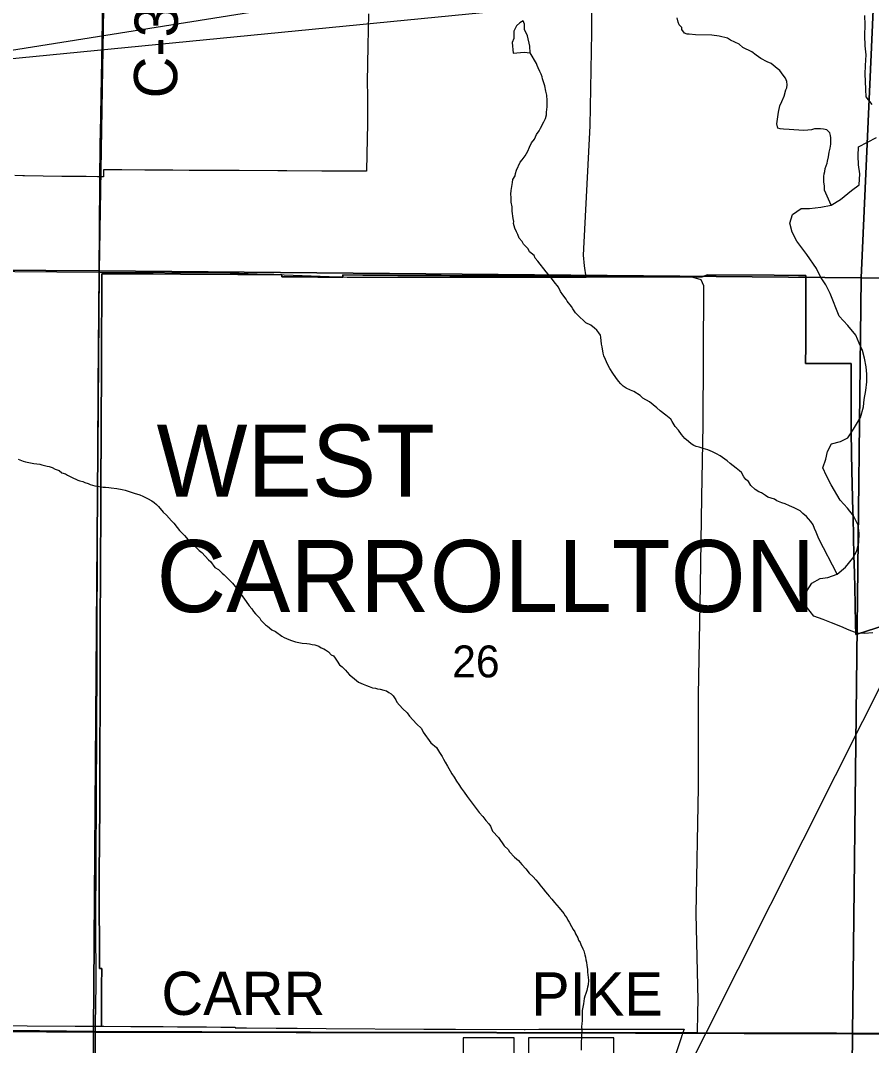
# Model space of a CAD drawing. Extents: x 0 to 34, y 0 to 22.
# Drawn here: x 3.924 to 5.042, y 14.765 to 16.112 of the extents above; entities that cross this region are included whole.
import ezdxf

# ---------------------------------------------------------------- set-up
doc = ezdxf.new("R2010")
doc.units = 0
for name, color, linetype in [('GM_X_Corporation_Text', 7, 'Continuous'), ('GM_X_County_Road', 7, 'Continuous'), ('GM_X_County_Road_Text', 7, 'Continuous'), ('GM_X_Interchange_Ramps', 7, 'Continuous'), ('GM_X_Interstate_Route', 7, 'Continuous'), ('GM_X_Minor_River', 7, 'Continuous'), ('GM_X_Rail_Line', 7, 'Continuous'), ('GM_X_Section', 7, 'Continuous'), ('GM_X_Section_Text', 7, 'Continuous'), ('GM_X_Township_Road', 7, 'Continuous'), ('SH_Text', 7, 'Continuous')]:
    doc.layers.add(name, color=color, linetype=linetype)

msp = doc.modelspace()

# ---------------------------------------------------------------- linework, layer by layer
at = {"layer": 'GM_X_County_Road'}
for p, q in [((3.042, 14.7898), (4.0225, 14.783)), ((4.0225, 14.783), (4.0227, 14.793)), ((4.0225, 14.783), (4.8137, 14.7815)), ((4.8137, 14.7815), (5.1801, 14.7808))]:
    msp.add_line(p, q, dxfattribs=at)
for points in [[(4.0289, 15.9515), (4.0291, 15.9644), (4.0311, 16.0847), (4.0341, 16.2506), (4.035, 16.2928), (4.0387, 16.4512)], [(4.0272, 15.7814), (4.0281, 15.8988), (4.0289, 15.9515)], [(4.0227, 14.793), (4.0235, 14.8451), (4.0229, 14.9278), (4.0237, 15.0898), (4.0246, 15.2692), (4.0252, 15.4538), (4.026, 15.6304), (4.0272, 15.7814)], [(4.0179, 13.9751), (4.0177, 14.0006), (4.0192, 14.1613), (4.0205, 14.2715), (4.0208, 14.4334), (4.0216, 14.5324), (4.0225, 14.6549), (4.0225, 14.783)]]:
    msp.add_lwpolyline(points, dxfattribs=at)
at = {"layer": 'GM_X_Interchange_Ramps'}
for points in [[(4.3812, 16.1209), (4.3805, 16.0788), (4.3797, 16.0313), (4.3798, 16.0136), (4.3798, 16.0023), (4.3799, 15.9845), (4.3798, 15.9765), (4.3792, 15.9365), (4.3789, 15.9141), (4.3329, 15.9143), (4.3202, 15.9144), (4.2738, 15.9147), (4.262, 15.9147), (4.2115, 15.915), (4.2038, 15.9151), (4.158, 15.9153), (4.1455, 15.9154), (4.124, 15.9155), (4.0947, 15.9157), (4.0872, 15.9157), (4.057, 15.9159), (4.033, 15.916), (4.0329, 15.9067), (4.0253, 15.9068), (4.0102, 15.9071), (3.9781, 15.9075), (3.9294, 15.9082), (3.9272, 15.9082), (3.9166, 15.9084)], [(3.8063, 14.7923), (3.9957, 14.791), (4.0303, 14.7908), (4.0303, 14.7938), (4.0303, 14.7939), (4.0303, 14.794), (4.0303, 14.7941), (4.0303, 14.7945), (4.0305, 14.8212), (4.0306, 14.844), (4.0308, 14.8667), (4.0279, 14.8667), (4.0279, 14.8765), (4.0277, 14.9008), (4.0276, 14.9109), (4.0275, 14.935), (4.0275, 14.9407), (4.0272, 14.9897), (4.0272, 14.9907), (4.0282, 15.079), (4.0282, 15.0822), (4.0283, 15.126), (4.0286, 15.241), (4.0287, 15.27), (4.0287, 15.2827), (4.0287, 15.2909), (4.0289, 15.3364), (4.0289, 15.347), (4.029, 15.3595), (4.029, 15.3667), (4.0291, 15.3873), (4.0292, 15.4131), (4.0294, 15.4525), (4.0296, 15.4906), (4.0296, 15.5103), (4.0297, 15.5125), (4.0297, 15.5285), (4.0298, 15.5447), (4.0299, 15.578), (4.0303, 15.6573), (4.0304, 15.6876), (4.0307, 15.7568), (4.0308, 15.7795), (4.057, 15.7794), (4.0985, 15.7792), (4.1344, 15.779), (4.2095, 15.7786), (4.2243, 15.7785), (4.2568, 15.7784), (4.2676, 15.7783), (4.2676, 15.7755), (4.2811, 15.7754), (4.296, 15.7753), (4.2965, 15.7753), (4.3148, 15.7752), (4.3168, 15.7752), (4.3477, 15.775), (4.3477, 15.7779), (4.3738, 15.7777), (4.3927, 15.7776), (4.397, 15.7775), (4.4084, 15.7775), (4.4198, 15.7774), (4.4311, 15.7773), (4.4425, 15.7772), (4.4434, 15.7772), (4.4539, 15.7772), (4.4652, 15.7771), (4.4766, 15.777), (4.488, 15.7769), (4.4993, 15.7769), (4.5107, 15.7768), (4.5354, 15.7768), (4.5385, 15.7768), (4.5441, 15.7768), (4.5764, 15.7768), (4.6037, 15.7767), (4.6335, 15.7765), (4.642, 15.7765), (4.6695, 15.7763), (4.686, 15.7762), (4.728, 15.776), (4.8118, 15.7755), (4.8161, 15.7755), (4.8199, 15.7755), (4.8231, 15.7767), (4.8256, 15.7776), (4.8273, 15.7783), (4.9143, 15.7776), (4.9462, 15.7774), (4.9542, 15.7773), (4.9562, 15.7773), (4.956, 15.7046), (4.9559, 15.685), (4.9558, 15.6617), (4.9749, 15.6616), (5.0157, 15.6614), (5.0154, 15.5733), (5.0155, 15.568), (5.016, 15.548), (5.0161, 15.5433), (5.0166, 15.521), (5.0179, 15.4669), (5.0181, 15.4598), (5.0193, 15.409), (5.0198, 15.3865), (5.0203, 15.3662), (5.0208, 15.3454), (5.0214, 15.3183), (5.0217, 15.3066), (5.0217, 15.3055), (5.0316, 15.3087), (5.071, 15.3213)], [(5.071, 15.3213), (5.0316, 15.3087), (5.0217, 15.3055), (5.0217, 15.3066), (5.0214, 15.3183), (5.0208, 15.3454), (5.0203, 15.3662), (5.0198, 15.3865), (5.0193, 15.409), (5.0181, 15.4598), (5.0179, 15.4669), (5.0166, 15.521), (5.0161, 15.5433), (5.016, 15.5444), (5.016, 15.548), (5.0155, 15.568), (5.0154, 15.5733), (5.0157, 15.6614), (4.9749, 15.6616), (4.9558, 15.6617), (4.9559, 15.685), (4.956, 15.7046), (4.9562, 15.7773), (4.9542, 15.7773), (4.9462, 15.7774), (4.9143, 15.7776), (4.8273, 15.7783), (4.8256, 15.7776), (4.8231, 15.7767), (4.8199, 15.7755), (4.8161, 15.7755), (4.8118, 15.7755), (4.728, 15.776), (4.686, 15.7762), (4.6695, 15.7763), (4.642, 15.7765), (4.6335, 15.7765), (4.6037, 15.7767), (4.5764, 15.7768), (4.5441, 15.7768), (4.5385, 15.7768), (4.5354, 15.7768), (4.5107, 15.7768), (4.4993, 15.7769), (4.488, 15.7769), (4.4766, 15.777), (4.4652, 15.7771), (4.4539, 15.7772), (4.4425, 15.7772), (4.4311, 15.7773), (4.4198, 15.7774), (4.4084, 15.7775), (4.397, 15.7775), (4.3927, 15.7776), (4.3738, 15.7777), (4.3477, 15.7779), (4.3477, 15.775), (4.3168, 15.7752), (4.3148, 15.7752), (4.296, 15.7753), (4.2811, 15.7754), (4.2676, 15.7755), (4.2676, 15.7783), (4.2568, 15.7784), (4.2243, 15.7785), (4.2095, 15.7786), (4.1344, 15.779), (4.0985, 15.7792), (4.057, 15.7794), (4.0308, 15.7795), (4.0307, 15.7568), (4.0304, 15.6876), (4.0303, 15.6573), (4.0299, 15.578), (4.0298, 15.5447), (4.0298, 15.5436), (4.0297, 15.5285), (4.0297, 15.5125), (4.0296, 15.5103), (4.0296, 15.4906), (4.0296, 15.4884), (4.0294, 15.4525), (4.0292, 15.4131), (4.0291, 15.3873), (4.029, 15.3667), (4.029, 15.3595), (4.0289, 15.347), (4.0289, 15.3364), (4.0287, 15.2909), (4.0287, 15.2827), (4.0287, 15.27), (4.0286, 15.241), (4.0283, 15.1277), (4.0283, 15.126), (4.0282, 15.0822), (4.0282, 15.079), (4.0272, 14.9907), (4.0272, 14.9897), (4.0275, 14.9407), (4.0275, 14.935), (4.0276, 14.9109), (4.0277, 14.9008), (4.0279, 14.8765), (4.0279, 14.8667), (4.0308, 14.8667), (4.0306, 14.844), (4.0305, 14.8212), (4.0303, 14.7945), (4.0303, 14.7944), (4.0303, 14.7943), (4.0303, 14.7941), (4.0303, 14.794), (4.0303, 14.7908), (4.0337, 14.7908), (4.0689, 14.7905), (4.0926, 14.7903), (4.1115, 14.7902), (4.1305, 14.7901), (4.1494, 14.7899), (4.1683, 14.7898), (4.1873, 14.7897), (4.2062, 14.7896), (4.2062, 14.7886), (4.2209, 14.7885), (4.26, 14.7883), (4.265, 14.7882), (4.2874, 14.7881), (4.3256, 14.7878), (4.4539, 14.7871), (4.4747, 14.787), (4.4956, 14.7869), (4.5858, 14.7866), (4.5874, 14.7866), (4.6051, 14.7867), (4.6717, 14.7869), (4.6907, 14.7869), (4.7637, 14.7871), (4.7906, 14.787), (4.7961, 14.787), (4.7941, 14.7813), (4.7935, 14.7795), (4.7932, 14.7784), (4.7922, 14.7756), (4.7922, 14.7756), (4.7749, 14.7247)], [(4.5722, 14.7351), (4.5727, 14.7753), (4.567, 14.7753), (4.5055, 14.7755), (4.505, 14.6575)], [(4.7035, 14.7423), (4.7039, 14.7756), (4.6894, 14.7755), (4.6714, 14.7755), (4.601, 14.7753), (4.5916, 14.7753), (4.5912, 14.7349)]]:
    msp.add_lwpolyline(points, dxfattribs=at)
at = {"layer": 'GM_X_Interstate_Route'}
for points in [[(5.1798, 14.7813), (4.8134, 14.782), (4.0223, 14.7835), (3.0418, 14.7903)], [(3.0418, 14.7903), (4.0223, 14.7835), (4.8134, 14.782), (5.1798, 14.7813)]]:
    msp.add_lwpolyline(points, dxfattribs=at)
at = {"layer": 'GM_X_Minor_River'}
for points in [[(4.5859, 16.0708), (4.5939, 16.0699), (4.5933, 16.0787), (4.5902, 16.0921), (4.5865, 16.1005), (4.5863, 16.1073), (4.5845, 16.1119), (4.5803, 16.1094), (4.576, 16.1053), (4.5724, 16.0981)], [(4.9891, 15.8696), (4.9807, 15.8894), (4.9807, 15.8925), (4.9804, 15.8952), (4.9798, 15.8997), (4.9795, 15.9043), (4.9796, 15.9074), (4.9801, 15.9108), (4.9809, 15.9138), (4.9814, 15.9176), (4.9839, 15.9248), (4.9843, 15.9275), (4.986, 15.9331), (4.9869, 15.9392), (4.9878, 15.9445), (4.9887, 15.9499), (4.9889, 15.9582), (4.9886, 15.9613), (4.9876, 15.9647), (4.9835, 15.9687), (4.9793, 15.9695), (4.9751, 15.97), (4.9713, 15.9701), (4.9675, 15.9698), (4.9633, 15.9688), (4.9587, 15.9681), (4.9533, 15.9679), (4.9469, 15.968), (4.9404, 15.9686), (4.9343, 15.9691), (4.9267, 15.9693), (4.9221, 15.9701), (4.9191, 15.9706), (4.9181, 15.9767), (4.919, 15.9828), (4.92, 15.9919), (4.9218, 16.0003), (4.9246, 16.0059), (4.9274, 16.0127), (4.9299, 16.021), (4.9311, 16.0237), (4.9316, 16.0279), (4.931, 16.0321), (4.9292, 16.0363), (4.9262, 16.0406), (4.9218, 16.0464), (4.9185, 16.0491), (4.9103, 16.0558), (4.905, 16.0579), (4.8967, 16.0622), (4.8907, 16.0666), (4.8851, 16.0709), (4.8731, 16.0769), (4.8686, 16.0812), (4.8569, 16.0865), (4.8532, 16.0892), (4.8422, 16.0918), (4.8327, 16.0928), (4.811, 16.0933), (4.8026, 16.0942), (4.7999, 16.0943), (4.7965, 16.0955), (4.7932, 16.1006), (4.7929, 16.1032), (4.7896, 16.1068), (4.7881, 16.1102), (4.7871, 16.1156)], [(5.043, 16.0021), (5.0352, 16.0118), (5.0347, 16.0217), (5.0346, 16.0324), (5.0341, 16.0419), (5.0345, 16.0533), (5.0352, 16.0673), (5.034, 16.0792), (5.0336, 16.0925), (5.034, 16.1066), (5.0336, 16.1188)], [(4.5724, 16.0981), (4.5722, 16.0886), (4.5702, 16.0833), (4.5714, 16.0692), (4.5859, 16.0708)], [(4.572, 15.8456), (4.5721, 15.8482), (4.5714, 15.8521), (4.5701, 15.8616), (4.5702, 15.8643), (4.5699, 15.8674), (4.5689, 15.8735), (4.5687, 15.8796), (4.5684, 15.8842), (4.569, 15.8891), (4.5704, 15.8994), (4.5712, 15.9032), (4.574, 15.9081), (4.5745, 15.9111), (4.5757, 15.9156), (4.5806, 15.9262), (4.5833, 15.9292), (4.5873, 15.9344), (4.5909, 15.9408), (4.5929, 15.9457), (4.5953, 15.9514), (4.5993, 15.9562), (4.6021, 15.9623), (4.6057, 15.9671), (4.6073, 15.9709), (4.6117, 15.9792), (4.6141, 15.9837), (4.6154, 15.9882), (4.6154, 15.9917), (4.616, 15.9989), (4.6162, 16.0073), (4.6156, 16.0142), (4.6143, 16.0195), (4.6129, 16.0264), (4.6111, 16.0318), (4.6101, 16.0356), (4.6094, 16.0383), (4.6084, 16.0418), (4.6065, 16.0452), (4.6044, 16.0503), (4.6029, 16.0533), (4.6019, 16.056), (4.5939, 16.0699)], [(5.0442, 15.3078), (5.0331, 15.3066), (5.0236, 15.3073), (5.013, 15.311), (5.0018, 15.3162), (4.9897, 15.3208), (4.9788, 15.3253), (4.9667, 15.3298), (4.9568, 15.3419), (4.9529, 15.3515), (4.9578, 15.3631), (4.9637, 15.3729), (4.9749, 15.379), (4.9849, 15.3803), (4.9972, 15.3849), (5.0081, 15.3941), (5.0179, 15.4056), (5.0231, 15.4153), (5.0257, 15.4263), (5.026, 15.4385), (5.0248, 15.4492), (5.0187, 15.4615), (5.0109, 15.4713), (5.0013, 15.4822), (4.9893, 15.5023), (4.9832, 15.5139), (4.9785, 15.5243), (4.9823, 15.536), (4.9844, 15.5458), (4.9897, 15.556), (5.0015, 15.5591), (5.0112, 15.5641), (5.0187, 15.5753), (5.0279, 15.5907), (5.0317, 15.6046), (5.0327, 15.6141), (5.035, 15.6259), (5.0364, 15.6376), (5.0363, 15.6475), (5.0351, 15.6571), (5.0331, 15.6685), (5.0303, 15.6785), (5.026, 15.6882), (5.0217, 15.6989), (5.0114, 15.7114), (5, 15.7239), (4.9882, 15.7535), (4.9824, 15.7651), (4.9755, 15.7756), (4.9701, 15.7864), (4.9573, 15.805), (4.944, 15.8225), (4.9379, 15.8341), (4.9352, 15.846), (4.9385, 15.8573), (4.9498, 15.8654), (4.9608, 15.8654), (4.9757, 15.8669), (4.9891, 15.8696), (5.0015, 15.8772), (5.0159, 15.889), (5.026, 15.8963), (5.0271, 15.9108), (5.0252, 15.9226), (5.0247, 15.9344), (5.0251, 15.9462), (5.049, 15.9585)], [(4.9972, 15.3849), (4.973, 15.431), (4.9712, 15.4356), (4.9698, 15.4398), (4.9676, 15.4449), (4.9655, 15.4495), (4.9625, 15.4541), (4.9596, 15.4576), (4.957, 15.4604), (4.9521, 15.4643), (4.9484, 15.4682), (4.9409, 15.4718), (4.9345, 15.4746), (4.9288, 15.4771), (4.9247, 15.4787), (4.9179, 15.4811), (4.9149, 15.4835), (4.9062, 15.486), (4.9032, 15.488), (4.8976, 15.4915), (4.8942, 15.4931), (4.8893, 15.4959), (4.8837, 15.5014), (4.8808, 15.5064), (4.877, 15.5092), (4.8745, 15.5127), (4.8716, 15.5185), (4.8689, 15.5204), (4.8645, 15.524), (4.8607, 15.5271), (4.8566, 15.5303), (4.8525, 15.5338), (4.8435, 15.5401), (4.8387, 15.5429), (4.8334, 15.5457), (4.8274, 15.5481), (4.8213, 15.5498), (4.816, 15.5515), (4.8118, 15.5527), (4.8088, 15.5539), (4.8054, 15.5559), (4.8017, 15.5591), (4.7972, 15.563), (4.7928, 15.5684), (4.7888, 15.5739), (4.7843, 15.5789), (4.7803, 15.5855), (4.7785, 15.5886), (4.7721, 15.5937), (4.7646, 15.5996), (4.7602, 15.6035), (4.7505, 15.6114), (4.7418, 15.6162), (4.7381, 15.6197), (4.7298, 15.6248), (4.7257, 15.6265), (4.7197, 15.6293), (4.7159, 15.6317), (4.7129, 15.6348), (4.71, 15.6383), (4.7063, 15.643), (4.7026, 15.6488), (4.6986, 15.655), (4.6953, 15.6608), (4.6928, 15.6669), (4.6906, 15.6715), (4.6896, 15.675), (4.6883, 15.6834), (4.6876, 15.6869), (4.6867, 15.696), (4.686, 15.6987), (4.6842, 15.7018), (4.6812, 15.7053), (4.6782, 15.7081), (4.6734, 15.712), (4.667, 15.7152), (4.664, 15.7183), (4.6592, 15.7226), (4.6532, 15.7281), (4.6499, 15.7335), (4.6481, 15.7366), (4.6426, 15.7436), (4.6411, 15.7463), (4.6367, 15.7518), (4.6337, 15.756), (4.6312, 15.7618), (4.6253, 15.7688), (4.6216, 15.7735), (4.615, 15.782), (4.6039, 15.796), (4.6002, 15.7999), (4.5991, 15.8034), (4.5928, 15.8085), (4.591, 15.8123), (4.585, 15.8182), (4.5832, 15.8217), (4.5795, 15.8263), (4.5774, 15.831), (4.5759, 15.8344), (4.5734, 15.8395), (4.572, 15.8456)], [(3.9209, 15.5359), (3.9277, 15.5331), (3.9307, 15.5322), (3.9372, 15.5309), (3.9417, 15.5304), (3.9493, 15.5291), (3.952, 15.5286), (3.9592, 15.5269), (3.9618, 15.5261), (3.9656, 15.5249), (3.9694, 15.5229), (3.975, 15.5208), (3.9784, 15.5181), (3.9833, 15.5165), (3.9859, 15.5149), (3.9912, 15.5124), (3.9938, 15.5109), (3.9969, 15.5096), (3.9995, 15.5084)], [(3.9995, 15.5084), (4.0021, 15.5076), (4.0059, 15.5064), (4.0086, 15.5052), (4.0127, 15.5039), (4.0154, 15.5027), (4.0184, 15.5019), (4.0218, 15.501), (4.0256, 15.5006), (4.0294, 15.4997), (4.0328, 15.4992), (4.0358, 15.4992), (4.04, 15.4987), (4.0431, 15.4982), (4.0507, 15.4973), (4.0575, 15.496), (4.0617, 15.4951), (4.067, 15.4935), (4.0734, 15.4914), (4.0806, 15.4889), (4.0847, 15.4873), (4.0911, 15.4841), (4.0968, 15.4813), (4.0997, 15.4789), (4.1027, 15.4762), (4.1053, 15.4738), (4.1116, 15.4664), (4.1157, 15.4625), (4.1224, 15.4548), (4.1254, 15.452), (4.1298, 15.4462), (4.1331, 15.4423), (4.1368, 15.438), (4.1394, 15.4357), (4.1442, 15.4298), (4.1469, 15.4282), (4.1587, 15.4158), (4.1621, 15.4134), (4.1665, 15.4083), (4.171, 15.4036), (4.1736, 15.4013), (4.1795, 15.3935), (4.1844, 15.3907), (4.1888, 15.3861), (4.1918, 15.3841), (4.2026, 15.3728), (4.2115, 15.3619), (4.214, 15.358), (4.2207, 15.3487), (4.2243, 15.3433), (4.228, 15.339), (4.2302, 15.3359), (4.2328, 15.3328), (4.2384, 15.3269), (4.2398, 15.3242), (4.2458, 15.318), (4.2484, 15.3164), (4.2544, 15.3117), (4.2593, 15.3093), (4.2675, 15.3033), (4.2705, 15.3017), (4.2765, 15.2989), (4.2803, 15.2977), (4.2852, 15.296), (4.294, 15.2943), (4.3004, 15.2938), (4.3038, 15.2933), (4.3073, 15.2925), (4.3107, 15.292), (4.316, 15.29), (4.319, 15.288), (4.3224, 15.2868), (4.325, 15.2852), (4.3287, 15.2828), (4.3324, 15.2789), (4.3351, 15.2773), (4.3377, 15.2742), (4.3402, 15.2703), (4.3432, 15.2657), (4.3465, 15.2629), (4.351, 15.2586), (4.3532, 15.2559), (4.3562, 15.2524), (4.3603, 15.2496), (4.3681, 15.243), (4.3745, 15.2401), (4.3787, 15.2385), (4.3824, 15.2373), (4.3866, 15.2356), (4.3904, 15.2348), (4.393, 15.234), (4.3965, 15.2335), (4.4014, 15.2322), (4.4048, 15.2314), (4.4082, 15.2294), (4.4112, 15.2274), (4.4138, 15.2247), (4.4174, 15.2196), (4.4185, 15.2166), (4.4259, 15.2084), (4.4323, 15.2025)], [(4.4323, 15.2025), (4.4352, 15.1983), (4.4445, 15.1881), (4.4508, 15.1819), (4.4533, 15.1772), (4.4633, 15.1633), (4.4707, 15.157), (4.4747, 15.1504), (4.478, 15.1454), (4.4799, 15.1419), (4.482, 15.1377), (4.4853, 15.1326), (4.4886, 15.1265), (4.4908, 15.1226), (4.4941, 15.1179), (4.497, 15.1129), (4.5, 15.1086), (4.5033, 15.1036), (4.5069, 15.0982), (4.511, 15.0928), (4.5161, 15.0858), (4.5217, 15.0784), (4.5268, 15.0718), (4.5317, 15.0663), (4.5357, 15.0609), (4.5394, 15.0566), (4.5416, 15.0535), (4.5441, 15.047), (4.5523, 15.0388), (4.5596, 15.0279), (4.5648, 15.0232), (4.5667, 15.0201), (4.573, 15.0127), (4.5786, 15.0084), (4.583, 15.0034), (4.5882, 14.9975), (4.5926, 14.9921), (4.5975, 14.987), (4.6012, 14.9831), (4.6041, 14.9796), (4.6063, 14.9765), (4.6108, 14.9711), (4.6137, 14.9675), (4.6167, 14.9644), (4.6189, 14.9617), (4.6222, 14.9578), (4.6259, 14.9535), (4.6319, 14.9465), (4.6378, 14.9388), (4.6396, 14.9357), (4.6418, 14.933), (4.6433, 14.9303), (4.6451, 14.9275), (4.648, 14.9218), (4.6502, 14.9179), (4.6524, 14.9148), (4.6535, 14.9121), (4.6564, 14.9067), (4.6574, 14.904), (4.6593, 14.9009), (4.6603, 14.8982), (4.6629, 14.8924), (4.6643, 14.8897), (4.6657, 14.8847), (4.6664, 14.8813), (4.6671, 14.8782), (4.6677, 14.8748), (4.6684, 14.8706), (4.669, 14.8656), (4.6689, 14.8618), (4.6699, 14.8549), (4.6702, 14.8511), (4.67, 14.845), (4.6692, 14.842), (4.6683, 14.8378), (4.6667, 14.8337), (4.6658, 14.8303), (4.6646, 14.8272), (4.6641, 14.8238), (4.6637, 14.82), (4.6628, 14.8159), (4.6623, 14.8113), (4.662, 14.7984), (4.6615, 14.7938), (4.6614, 14.7904), (4.6616, 14.7858), (4.6614, 14.7759), (4.6608, 14.7698), (4.6606, 14.7592)]]:
    msp.add_lwpolyline(points, dxfattribs=at)
at = {"layer": 'GM_X_Rail_Line'}
msp.add_lwpolyline([(4.4322, 14.0019), (4.4704, 14.0782), (4.5412, 14.2186), (4.6196, 14.374), (4.8244, 14.781), (4.9948, 15.1204), (5.1022, 15.3337)], dxfattribs=at)
at = {"layer": 'GM_X_Section'}
for points in [[(3.0664, 16.7946), (4.0439, 16.7912), (4.0274, 15.7833), (3.0481, 15.7894)], [(4.0439, 16.7912), (5.0741, 16.7917), (5.0286, 15.7742), (4.0274, 15.7833)], [(5.0741, 16.7917), (6.0948, 16.7898), (6.0861, 15.9241), (5.7249, 15.8958), (5.3975, 15.7702), (5.0286, 15.7742)], [(3.0481, 15.7894), (4.0274, 15.7833), (4.0198, 14.784), (3.0289, 14.7963)], [(4.0274, 15.7833), (5.0286, 15.7742), (5.0174, 14.7806), (4.0198, 14.784)], [(5.0286, 15.7742), (5.3975, 15.7702), (5.203, 15.1969), (5.5176, 14.7755), (5.0174, 14.7806)], [(5.0174, 14.7806), (5.5176, 14.7755), (5.3974, 14.4862), (5.0124, 14.305)]]:
    msp.add_lwpolyline(points, close=True, dxfattribs=at)
for points in [[(3.0071, 14.0019), (3.0289, 14.7963), (4.0198, 14.784), (4.0152, 14.0019)], [(4.0152, 14.0019), (4.0198, 14.784), (5.0174, 14.7806), (5.0124, 14.305), (4.8242, 14.0019)]]:
    msp.add_lwpolyline(points, dxfattribs=at)
at = {"layer": 'GM_X_Township_Road'}
for points in [[(4.8221, 15.7638), (4.8184, 15.7715), (4.8079, 15.7748), (4.6675, 15.7752), (4.6653, 15.79), (4.6638, 15.8041), (4.6727, 15.9738), (4.6746, 16.0964), (4.6756, 16.2113), (4.6765, 16.2777), (4.6763, 16.2796)], [(3.5622, 15.8032), (3.5772, 15.7973), (3.6188, 15.7869), (3.627, 15.7856), (3.6382, 15.7845), (4.0272, 15.7814), (4.1995, 15.7808), (4.3534, 15.7752), (4.5245, 15.7749), (4.6675, 15.7752)], [(4.8137, 14.7815), (4.814, 14.8089), (4.8147, 14.8252), (4.812, 14.9385), (4.8151, 15.1049), (4.8151, 15.2257), (4.8177, 15.3697), (4.8195, 15.486), (4.8213, 15.581), (4.822, 15.7628), (4.8221, 15.7638)]]:
    msp.add_lwpolyline(points, dxfattribs=at)
at = {"layer": 'SH_Text'}
msp.add_lwpolyline([(9.6169, 16.9806), (3.7384, 16.0451), (9.6169, 16.6206)], close=True, dxfattribs=at)

# ---------------------------------------------------------------- texts
at = {"layer": 'GM_X_Corporation_Text'}
for s, p in [('WEST', (4.1028, 15.4866)), ('CARROLLTON', (4.1028, 15.3349))]:
    msp.add_text(s, height=0.0947, rotation=0, dxfattribs=at).set_placement(p)
at = {"layer": 'GM_X_County_Road_Text'}
for s, rotation, p in [('C-37', 89.3142, (4.1296, 16.0096)), ('CARR', 0, (4.1092, 14.8056)), ('PIKE', 0, (4.595, 14.8048))]:
    msp.add_text(s, height=0.05682, rotation=rotation, dxfattribs=at).set_placement(p)
at = {"layer": 'GM_X_Section_Text'}
msp.add_text('26', height=0.04186, rotation=0, dxfattribs=at).set_placement((4.4913, 15.2492))

doc.saveas('drawing.dxf')
